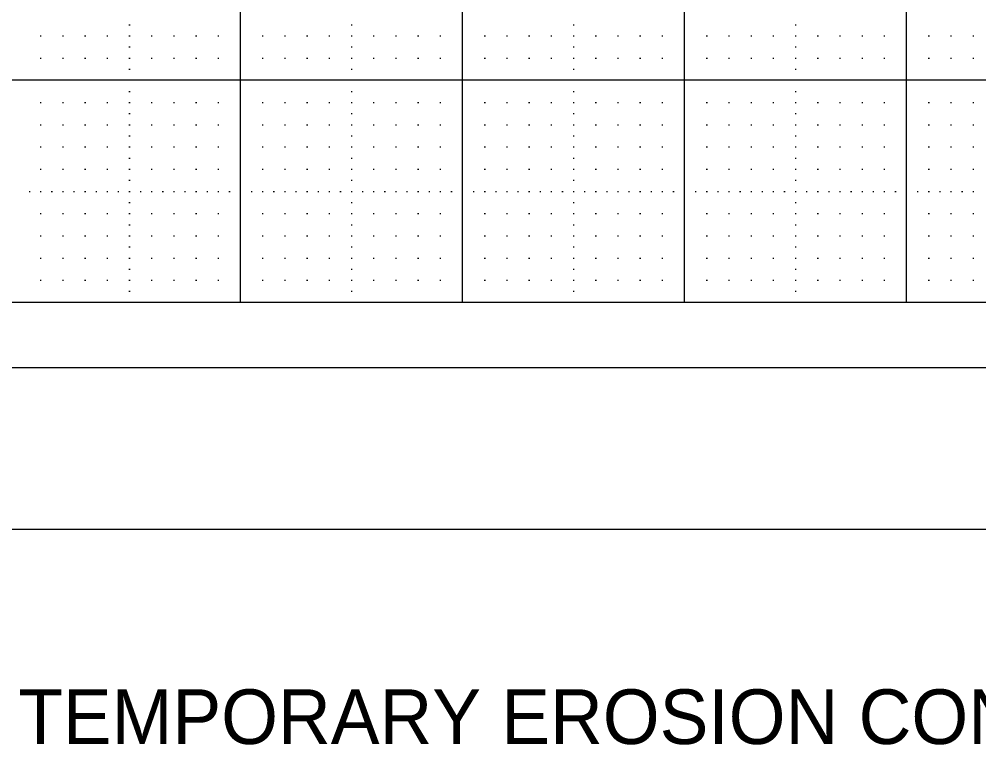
# Model space of a CAD drawing. Extents: x -1.6 to 32.7, y -1.7 to 21.9.
# Drawn here: x 23.748 to 28.07, y -1.698 to 1.568 of the extents above; entities that cross this region are included whole.
import ezdxf

# ---------------------------------------------------------------- set-up
doc = ezdxf.new("R2010")
doc.units = 0
for name, color, linetype in [('Level 1', 7, 'Continuous'), ('Level 4', 7, 'Continuous'), ('Level 5', 7, 'Continuous'), ('Level 63', 7, 'Continuous'), ('R_Border_Dark', 7, 'Continuous'), ('TYPICAL FONT', 7, 'Continuous')]:
    doc.layers.add(name, color=color, linetype=linetype)

msp = doc.modelspace()

# ---------------------------------------------------------------- linework, layer by layer
at = {"layer": 'Level 1'}
msp.add_line((31.617, -0.001), (-0.001, -0.001), dxfattribs=at)
msp.add_lwpolyline([(0.745, 11.3072), (30.745, 11.3072), (30.745, 0.293), (0.745, 0.293)], close=True, dxfattribs=at)
at = {"layer": 'Level 4'}
msp.add_line((31.617, 0.293), (-0.001, 0.293), dxfattribs=at)
at = {"layer": 'Level 5'}
for p, q in [((24.2425, 1.543), (24.2475, 1.543)), ((25.2425, 1.543), (25.2475, 1.543)), ((26.2425, 1.543), (26.2475, 1.543)), ((27.2425, 1.543), (27.2475, 1.543)), ((23.8425, 1.493), (23.8475, 1.493)), ((23.9425, 1.493), (23.9475, 1.493)), ((24.0425, 1.493), (24.0475, 1.493)), ((24.1425, 1.493), (24.1475, 1.493)), ((24.2425, 1.493), (24.2475, 1.493)), ((24.3425, 1.493), (24.3475, 1.493)), ((24.4425, 1.493), (24.4475, 1.493)), ((24.5425, 1.493), (24.5475, 1.493)), ((24.6425, 1.493), (24.6475, 1.493)), ((24.8425, 1.493), (24.8475, 1.493)), ((24.9425, 1.493), (24.9475, 1.493)), ((25.0425, 1.493), (25.0475, 1.493)), ((25.1425, 1.493), (25.1475, 1.493)), ((25.2425, 1.493), (25.2475, 1.493)), ((25.3425, 1.493), (25.3475, 1.493)), ((25.4425, 1.493), (25.4475, 1.493)), ((25.5425, 1.493), (25.5475, 1.493)), ((25.6425, 1.493), (25.6475, 1.493)), ((25.8425, 1.493), (25.8475, 1.493)), ((25.9425, 1.493), (25.9475, 1.493)), ((26.0425, 1.493), (26.0475, 1.493)), ((26.1425, 1.493), (26.1475, 1.493)), ((26.2425, 1.493), (26.2475, 1.493)), ((26.3425, 1.493), (26.3475, 1.493)), ((26.4425, 1.493), (26.4475, 1.493)), ((26.5425, 1.493), (26.5475, 1.493)), ((26.6425, 1.493), (26.6475, 1.493)), ((26.8425, 1.493), (26.8475, 1.493)), ((26.9425, 1.493), (26.9475, 1.493)), ((27.0425, 1.493), (27.0475, 1.493)), ((27.1425, 1.493), (27.1475, 1.493)), ((27.2425, 1.493), (27.2475, 1.493)), ((27.3425, 1.493), (27.3475, 1.493)), ((27.4425, 1.493), (27.4475, 1.493)), ((27.5425, 1.493), (27.5475, 1.493)), ((27.6425, 1.493), (27.6475, 1.493)), ((27.8425, 1.493), (27.8475, 1.493)), ((27.9425, 1.493), (27.9475, 1.493)), ((28.0425, 1.493), (28.0475, 1.493)), ((24.2425, 1.443), (24.2475, 1.443)), ((25.2425, 1.443), (25.2475, 1.443)), ((26.2425, 1.443), (26.2475, 1.443)), ((27.2425, 1.443), (27.2475, 1.443)), ((23.8425, 1.393), (23.8475, 1.393)), ((23.9425, 1.393), (23.9475, 1.393)), ((24.0425, 1.393), (24.0475, 1.393)), ((24.1425, 1.393), (24.1475, 1.393)), ((24.2425, 1.393), (24.2475, 1.393)), ((24.3425, 1.393), (24.3475, 1.393)), ((24.4425, 1.393), (24.4475, 1.393)), ((24.5425, 1.393), (24.5475, 1.393)), ((24.6425, 1.393), (24.6475, 1.393)), ((24.8425, 1.393), (24.8475, 1.393)), ((24.9425, 1.393), (24.9475, 1.393)), ((25.0425, 1.393), (25.0475, 1.393)), ((25.1425, 1.393), (25.1475, 1.393)), ((25.2425, 1.393), (25.2475, 1.393)), ((25.3425, 1.393), (25.3475, 1.393)), ((25.4425, 1.393), (25.4475, 1.393)), ((25.5425, 1.393), (25.5475, 1.393)), ((25.6425, 1.393), (25.6475, 1.393)), ((25.8425, 1.393), (25.8475, 1.393)), ((25.9425, 1.393), (25.9475, 1.393)), ((26.0425, 1.393), (26.0475, 1.393)), ((26.1425, 1.393), (26.1475, 1.393)), ((26.2425, 1.393), (26.2475, 1.393)), ((26.3425, 1.393), (26.3475, 1.393)), ((26.4425, 1.393), (26.4475, 1.393)), ((26.5425, 1.393), (26.5475, 1.393)), ((26.6425, 1.393), (26.6475, 1.393)), ((26.8425, 1.393), (26.8475, 1.393)), ((26.9425, 1.393), (26.9475, 1.393)), ((27.0425, 1.393), (27.0475, 1.393)), ((27.1425, 1.393), (27.1475, 1.393)), ((27.2425, 1.393), (27.2475, 1.393)), ((27.3425, 1.393), (27.3475, 1.393)), ((27.4425, 1.393), (27.4475, 1.393)), ((27.5425, 1.393), (27.5475, 1.393)), ((27.6425, 1.393), (27.6475, 1.393)), ((27.8425, 1.393), (27.8475, 1.393)), ((27.9425, 1.393), (27.9475, 1.393)), ((28.0425, 1.393), (28.0475, 1.393)), ((24.2425, 1.343), (24.2475, 1.343)), ((25.2425, 1.343), (25.2475, 1.343)), ((26.2425, 1.343), (26.2475, 1.343)), ((27.2425, 1.343), (27.2475, 1.343)), ((24.2425, 1.243), (24.2475, 1.243)), ((25.2425, 1.243), (25.2475, 1.243)), ((26.2425, 1.243), (26.2475, 1.243)), ((27.2425, 1.243), (27.2475, 1.243)), ((23.8425, 1.193), (23.8475, 1.193)), ((23.9425, 1.193), (23.9475, 1.193)), ((24.0425, 1.193), (24.0475, 1.193)), ((24.1425, 1.193), (24.1475, 1.193)), ((24.2425, 1.193), (24.2475, 1.193)), ((24.3425, 1.193), (24.3475, 1.193)), ((24.4425, 1.193), (24.4475, 1.193)), ((24.5425, 1.193), (24.5475, 1.193)), ((24.6425, 1.193), (24.6475, 1.193)), ((24.8425, 1.193), (24.8475, 1.193)), ((24.9425, 1.193), (24.9475, 1.193)), ((25.0425, 1.193), (25.0475, 1.193)), ((25.1425, 1.193), (25.1475, 1.193)), ((25.2425, 1.193), (25.2475, 1.193)), ((25.3425, 1.193), (25.3475, 1.193)), ((25.4425, 1.193), (25.4475, 1.193)), ((25.5425, 1.193), (25.5475, 1.193)), ((25.6425, 1.193), (25.6475, 1.193)), ((25.8425, 1.193), (25.8475, 1.193)), ((25.9425, 1.193), (25.9475, 1.193)), ((26.0425, 1.193), (26.0475, 1.193)), ((26.1425, 1.193), (26.1475, 1.193)), ((26.2425, 1.193), (26.2475, 1.193)), ((26.3425, 1.193), (26.3475, 1.193)), ((26.4425, 1.193), (26.4475, 1.193)), ((26.5425, 1.193), (26.5475, 1.193)), ((26.6425, 1.193), (26.6475, 1.193)), ((26.8425, 1.193), (26.8475, 1.193)), ((26.9425, 1.193), (26.9475, 1.193)), ((27.0425, 1.193), (27.0475, 1.193)), ((27.1425, 1.193), (27.1475, 1.193)), ((27.2425, 1.193), (27.2475, 1.193)), ((27.3425, 1.193), (27.3475, 1.193)), ((27.4425, 1.193), (27.4475, 1.193)), ((27.5425, 1.193), (27.5475, 1.193)), ((27.6425, 1.193), (27.6475, 1.193)), ((27.8425, 1.193), (27.8475, 1.193)), ((27.9425, 1.193), (27.9475, 1.193)), ((28.0425, 1.193), (28.0475, 1.193)), ((24.2425, 1.143), (24.2475, 1.143)), ((25.2425, 1.143), (25.2475, 1.143)), ((26.2425, 1.143), (26.2475, 1.143)), ((27.2425, 1.143), (27.2475, 1.143)), ((23.8425, 1.093), (23.8475, 1.093)), ((23.9425, 1.093), (23.9475, 1.093)), ((24.0425, 1.093), (24.0475, 1.093)), ((24.1425, 1.093), (24.1475, 1.093)), ((24.2425, 1.093), (24.2475, 1.093)), ((24.3425, 1.093), (24.3475, 1.093)), ((24.4425, 1.093), (24.4475, 1.093)), ((24.5425, 1.093), (24.5475, 1.093)), ((24.6425, 1.093), (24.6475, 1.093)), ((24.8425, 1.093), (24.8475, 1.093)), ((24.9425, 1.093), (24.9475, 1.093)), ((25.0425, 1.093), (25.0475, 1.093)), ((25.1425, 1.093), (25.1475, 1.093)), ((25.2425, 1.093), (25.2475, 1.093)), ((25.3425, 1.093), (25.3475, 1.093)), ((25.4425, 1.093), (25.4475, 1.093)), ((25.5425, 1.093), (25.5475, 1.093)), ((25.6425, 1.093), (25.6475, 1.093)), ((25.8425, 1.093), (25.8475, 1.093)), ((25.9425, 1.093), (25.9475, 1.093)), ((26.0425, 1.093), (26.0475, 1.093)), ((26.1425, 1.093), (26.1475, 1.093)), ((26.2425, 1.093), (26.2475, 1.093)), ((26.3425, 1.093), (26.3475, 1.093)), ((26.4425, 1.093), (26.4475, 1.093)), ((26.5425, 1.093), (26.5475, 1.093)), ((26.6425, 1.093), (26.6475, 1.093)), ((26.8425, 1.093), (26.8475, 1.093)), ((26.9425, 1.093), (26.9475, 1.093)), ((27.0425, 1.093), (27.0475, 1.093)), ((27.1425, 1.093), (27.1475, 1.093)), ((27.2425, 1.093), (27.2475, 1.093)), ((27.3425, 1.093), (27.3475, 1.093)), ((27.4425, 1.093), (27.4475, 1.093)), ((27.5425, 1.093), (27.5475, 1.093)), ((27.6425, 1.093), (27.6475, 1.093)), ((27.8425, 1.093), (27.8475, 1.093)), ((27.9425, 1.093), (27.9475, 1.093)), ((28.0425, 1.093), (28.0475, 1.093)), ((24.2425, 1.043), (24.2475, 1.043)), ((25.2425, 1.043), (25.2475, 1.043)), ((26.2425, 1.043), (26.2475, 1.043)), ((27.2425, 1.043), (27.2475, 1.043)), ((23.8425, 0.993), (23.8475, 0.993)), ((23.9425, 0.993), (23.9475, 0.993)), ((24.0425, 0.993), (24.0475, 0.993)), ((24.1425, 0.993), (24.1475, 0.993)), ((24.2425, 0.993), (24.2475, 0.993)), ((24.3425, 0.993), (24.3475, 0.993)), ((24.4425, 0.993), (24.4475, 0.993)), ((24.5425, 0.993), (24.5475, 0.993)), ((24.6425, 0.993), (24.6475, 0.993)), ((24.8425, 0.993), (24.8475, 0.993)), ((24.9425, 0.993), (24.9475, 0.993)), ((25.0425, 0.993), (25.0475, 0.993)), ((25.1425, 0.993), (25.1475, 0.993)), ((25.2425, 0.993), (25.2475, 0.993)), ((25.3425, 0.993), (25.3475, 0.993)), ((25.4425, 0.993), (25.4475, 0.993)), ((25.5425, 0.993), (25.5475, 0.993)), ((25.6425, 0.993), (25.6475, 0.993)), ((25.8425, 0.993), (25.8475, 0.993)), ((25.9425, 0.993), (25.9475, 0.993)), ((26.0425, 0.993), (26.0475, 0.993)), ((26.1425, 0.993), (26.1475, 0.993)), ((26.2425, 0.993), (26.2475, 0.993)), ((26.3425, 0.993), (26.3475, 0.993)), ((26.4425, 0.993), (26.4475, 0.993)), ((26.5425, 0.993), (26.5475, 0.993)), ((26.6425, 0.993), (26.6475, 0.993)), ((26.8425, 0.993), (26.8475, 0.993)), ((26.9425, 0.993), (26.9475, 0.993)), ((27.0425, 0.993), (27.0475, 0.993)), ((27.1425, 0.993), (27.1475, 0.993)), ((27.2425, 0.993), (27.2475, 0.993)), ((27.3425, 0.993), (27.3475, 0.993)), ((27.4425, 0.993), (27.4475, 0.993)), ((27.5425, 0.993), (27.5475, 0.993)), ((27.6425, 0.993), (27.6475, 0.993)), ((27.8425, 0.993), (27.8475, 0.993)), ((27.9425, 0.993), (27.9475, 0.993)), ((28.0425, 0.993), (28.0475, 0.993)), ((24.2425, 0.943), (24.2475, 0.943)), ((25.2425, 0.943), (25.2475, 0.943)), ((26.2425, 0.943), (26.2475, 0.943)), ((27.2425, 0.943), (27.2475, 0.943)), ((23.8425, 0.893), (23.8475, 0.893)), ((23.9425, 0.893), (23.9475, 0.893)), ((24.0425, 0.893), (24.0475, 0.893)), ((24.1425, 0.893), (24.1475, 0.893)), ((24.2425, 0.893), (24.2475, 0.893)), ((24.3425, 0.893), (24.3475, 0.893)), ((24.4425, 0.893), (24.4475, 0.893)), ((24.5425, 0.893), (24.5475, 0.893)), ((24.6425, 0.893), (24.6475, 0.893)), ((24.8425, 0.893), (24.8475, 0.893)), ((24.9425, 0.893), (24.9475, 0.893)), ((25.0425, 0.893), (25.0475, 0.893)), ((25.1425, 0.893), (25.1475, 0.893)), ((25.2425, 0.893), (25.2475, 0.893)), ((25.3425, 0.893), (25.3475, 0.893)), ((25.4425, 0.893), (25.4475, 0.893)), ((25.5425, 0.893), (25.5475, 0.893)), ((25.6425, 0.893), (25.6475, 0.893)), ((25.8425, 0.893), (25.8475, 0.893)), ((25.9425, 0.893), (25.9475, 0.893)), ((26.0425, 0.893), (26.0475, 0.893)), ((26.1425, 0.893), (26.1475, 0.893)), ((26.2425, 0.893), (26.2475, 0.893)), ((26.3425, 0.893), (26.3475, 0.893)), ((26.4425, 0.893), (26.4475, 0.893)), ((26.5425, 0.893), (26.5475, 0.893)), ((26.6425, 0.893), (26.6475, 0.893)), ((26.8425, 0.893), (26.8475, 0.893)), ((26.9425, 0.893), (26.9475, 0.893)), ((27.0425, 0.893), (27.0475, 0.893)), ((27.1425, 0.893), (27.1475, 0.893)), ((27.2425, 0.893), (27.2475, 0.893)), ((27.3425, 0.893), (27.3475, 0.893)), ((27.4425, 0.893), (27.4475, 0.893)), ((27.5425, 0.893), (27.5475, 0.893)), ((27.6425, 0.893), (27.6475, 0.893)), ((27.8425, 0.893), (27.8475, 0.893)), ((27.9425, 0.893), (27.9475, 0.893)), ((28.0425, 0.893), (28.0475, 0.893)), ((24.2425, 0.843), (24.2475, 0.843)), ((25.2425, 0.843), (25.2475, 0.843)), ((26.2425, 0.843), (26.2475, 0.843)), ((27.2425, 0.843), (27.2475, 0.843)), ((23.7925, 0.793), (23.7975, 0.793)), ((23.8425, 0.793), (23.8475, 0.793)), ((23.8925, 0.793), (23.8975, 0.793)), ((23.9425, 0.793), (23.9475, 0.793)), ((23.9925, 0.793), (23.9975, 0.793)), ((24.0425, 0.793), (24.0475, 0.793)), ((24.0925, 0.793), (24.0975, 0.793)), ((24.1425, 0.793), (24.1475, 0.793)), ((24.1925, 0.793), (24.1975, 0.793)), ((24.2425, 0.793), (24.2475, 0.793)), ((24.2925, 0.793), (24.2975, 0.793)), ((24.3425, 0.793), (24.3475, 0.793)), ((24.3925, 0.793), (24.3975, 0.793)), ((24.4425, 0.793), (24.4475, 0.793)), ((24.4925, 0.793), (24.4975, 0.793)), ((24.5425, 0.793), (24.5475, 0.793)), ((24.5925, 0.793), (24.5975, 0.793)), ((24.6425, 0.793), (24.6475, 0.793)), ((24.6925, 0.793), (24.6975, 0.793)), ((24.7925, 0.793), (24.7975, 0.793)), ((24.8425, 0.793), (24.8475, 0.793)), ((24.8925, 0.793), (24.8975, 0.793)), ((24.9425, 0.793), (24.9475, 0.793)), ((24.9925, 0.793), (24.9975, 0.793)), ((25.0425, 0.793), (25.0475, 0.793)), ((25.0925, 0.793), (25.0975, 0.793)), ((25.1425, 0.793), (25.1475, 0.793)), ((25.1925, 0.793), (25.1975, 0.793)), ((25.2425, 0.793), (25.2475, 0.793)), ((25.2925, 0.793), (25.2975, 0.793)), ((25.3425, 0.793), (25.3475, 0.793)), ((25.3925, 0.793), (25.3975, 0.793)), ((25.4425, 0.793), (25.4475, 0.793)), ((25.4925, 0.793), (25.4975, 0.793)), ((25.5425, 0.793), (25.5475, 0.793)), ((25.5925, 0.793), (25.5975, 0.793)), ((25.6425, 0.793), (25.6475, 0.793)), ((25.6925, 0.793), (25.6975, 0.793)), ((25.7925, 0.793), (25.7975, 0.793)), ((25.8425, 0.793), (25.8475, 0.793)), ((25.8925, 0.793), (25.8975, 0.793)), ((25.9425, 0.793), (25.9475, 0.793)), ((25.9925, 0.793), (25.9975, 0.793)), ((26.0425, 0.793), (26.0475, 0.793)), ((26.0925, 0.793), (26.0975, 0.793)), ((26.1425, 0.793), (26.1475, 0.793)), ((26.1925, 0.793), (26.1975, 0.793)), ((26.2425, 0.793), (26.2475, 0.793)), ((26.2925, 0.793), (26.2975, 0.793)), ((26.3425, 0.793), (26.3475, 0.793)), ((26.3925, 0.793), (26.3975, 0.793)), ((26.4425, 0.793), (26.4475, 0.793)), ((26.4925, 0.793), (26.4975, 0.793)), ((26.5425, 0.793), (26.5475, 0.793)), ((26.5925, 0.793), (26.5975, 0.793)), ((26.6425, 0.793), (26.6475, 0.793)), ((26.6925, 0.793), (26.6975, 0.793)), ((26.7925, 0.793), (26.7975, 0.793)), ((26.8425, 0.793), (26.8475, 0.793)), ((26.8925, 0.793), (26.8975, 0.793)), ((26.9425, 0.793), (26.9475, 0.793)), ((26.9925, 0.793), (26.9975, 0.793)), ((27.0425, 0.793), (27.0475, 0.793)), ((27.0925, 0.793), (27.0975, 0.793)), ((27.1425, 0.793), (27.1475, 0.793)), ((27.1925, 0.793), (27.1975, 0.793)), ((27.2425, 0.793), (27.2475, 0.793)), ((27.2925, 0.793), (27.2975, 0.793)), ((27.3425, 0.793), (27.3475, 0.793)), ((27.3925, 0.793), (27.3975, 0.793)), ((27.4425, 0.793), (27.4475, 0.793)), ((27.4925, 0.793), (27.4975, 0.793)), ((27.5425, 0.793), (27.5475, 0.793)), ((27.5925, 0.793), (27.5975, 0.793)), ((27.6425, 0.793), (27.6475, 0.793)), ((27.6925, 0.793), (27.6975, 0.793)), ((27.7925, 0.793), (27.7975, 0.793)), ((27.8425, 0.793), (27.8475, 0.793)), ((27.8925, 0.793), (27.8975, 0.793)), ((27.9425, 0.793), (27.9475, 0.793)), ((27.9925, 0.793), (27.9975, 0.793)), ((28.0425, 0.793), (28.0475, 0.793)), ((24.2425, 0.743), (24.2475, 0.743)), ((25.2425, 0.743), (25.2475, 0.743)), ((26.2425, 0.743), (26.2475, 0.743)), ((27.2425, 0.743), (27.2475, 0.743)), ((23.8425, 0.693), (23.8475, 0.693)), ((23.9425, 0.693), (23.9475, 0.693)), ((24.0425, 0.693), (24.0475, 0.693)), ((24.1425, 0.693), (24.1475, 0.693)), ((24.2425, 0.693), (24.2475, 0.693)), ((24.3425, 0.693), (24.3475, 0.693)), ((24.4425, 0.693), (24.4475, 0.693)), ((24.5425, 0.693), (24.5475, 0.693)), ((24.6425, 0.693), (24.6475, 0.693)), ((24.8425, 0.693), (24.8475, 0.693)), ((24.9425, 0.693), (24.9475, 0.693)), ((25.0425, 0.693), (25.0475, 0.693)), ((25.1425, 0.693), (25.1475, 0.693)), ((25.2425, 0.693), (25.2475, 0.693)), ((25.3425, 0.693), (25.3475, 0.693)), ((25.4425, 0.693), (25.4475, 0.693)), ((25.5425, 0.693), (25.5475, 0.693)), ((25.6425, 0.693), (25.6475, 0.693)), ((25.8425, 0.693), (25.8475, 0.693)), ((25.9425, 0.693), (25.9475, 0.693)), ((26.0425, 0.693), (26.0475, 0.693)), ((26.1425, 0.693), (26.1475, 0.693)), ((26.2425, 0.693), (26.2475, 0.693)), ((26.3425, 0.693), (26.3475, 0.693)), ((26.4425, 0.693), (26.4475, 0.693)), ((26.5425, 0.693), (26.5475, 0.693)), ((26.6425, 0.693), (26.6475, 0.693)), ((26.8425, 0.693), (26.8475, 0.693)), ((26.9425, 0.693), (26.9475, 0.693)), ((27.0425, 0.693), (27.0475, 0.693)), ((27.1425, 0.693), (27.1475, 0.693)), ((27.2425, 0.693), (27.2475, 0.693)), ((27.3425, 0.693), (27.3475, 0.693)), ((27.4425, 0.693), (27.4475, 0.693)), ((27.5425, 0.693), (27.5475, 0.693)), ((27.6425, 0.693), (27.6475, 0.693)), ((27.8425, 0.693), (27.8475, 0.693)), ((27.9425, 0.693), (27.9475, 0.693)), ((28.0425, 0.693), (28.0475, 0.693)), ((24.2425, 0.643), (24.2475, 0.643)), ((25.2425, 0.643), (25.2475, 0.643)), ((26.2425, 0.643), (26.2475, 0.643)), ((27.2425, 0.643), (27.2475, 0.643)), ((23.8425, 0.593), (23.8475, 0.593)), ((23.9425, 0.593), (23.9475, 0.593)), ((24.0425, 0.593), (24.0475, 0.593)), ((24.1425, 0.593), (24.1475, 0.593)), ((24.2425, 0.593), (24.2475, 0.593)), ((24.3425, 0.593), (24.3475, 0.593)), ((24.4425, 0.593), (24.4475, 0.593)), ((24.5425, 0.593), (24.5475, 0.593)), ((24.6425, 0.593), (24.6475, 0.593)), ((24.8425, 0.593), (24.8475, 0.593)), ((24.9425, 0.593), (24.9475, 0.593)), ((25.0425, 0.593), (25.0475, 0.593)), ((25.1425, 0.593), (25.1475, 0.593)), ((25.2425, 0.593), (25.2475, 0.593)), ((25.3425, 0.593), (25.3475, 0.593)), ((25.4425, 0.593), (25.4475, 0.593)), ((25.5425, 0.593), (25.5475, 0.593)), ((25.6425, 0.593), (25.6475, 0.593)), ((25.8425, 0.593), (25.8475, 0.593)), ((25.9425, 0.593), (25.9475, 0.593)), ((26.0425, 0.593), (26.0475, 0.593)), ((26.1425, 0.593), (26.1475, 0.593)), ((26.2425, 0.593), (26.2475, 0.593)), ((26.3425, 0.593), (26.3475, 0.593)), ((26.4425, 0.593), (26.4475, 0.593)), ((26.5425, 0.593), (26.5475, 0.593)), ((26.6425, 0.593), (26.6475, 0.593)), ((26.8425, 0.593), (26.8475, 0.593)), ((26.9425, 0.593), (26.9475, 0.593)), ((27.0425, 0.593), (27.0475, 0.593)), ((27.1425, 0.593), (27.1475, 0.593)), ((27.2425, 0.593), (27.2475, 0.593)), ((27.3425, 0.593), (27.3475, 0.593)), ((27.4425, 0.593), (27.4475, 0.593)), ((27.5425, 0.593), (27.5475, 0.593)), ((27.6425, 0.593), (27.6475, 0.593)), ((27.8425, 0.593), (27.8475, 0.593)), ((27.9425, 0.593), (27.9475, 0.593)), ((28.0425, 0.593), (28.0475, 0.593)), ((24.2425, 0.543), (24.2475, 0.543)), ((25.2425, 0.543), (25.2475, 0.543)), ((26.2425, 0.543), (26.2475, 0.543)), ((27.2425, 0.543), (27.2475, 0.543)), ((23.8425, 0.493), (23.8475, 0.493)), ((23.9425, 0.493), (23.9475, 0.493)), ((24.0425, 0.493), (24.0475, 0.493)), ((24.1425, 0.493), (24.1475, 0.493)), ((24.2425, 0.493), (24.2475, 0.493)), ((24.3425, 0.493), (24.3475, 0.493)), ((24.4425, 0.493), (24.4475, 0.493)), ((24.5425, 0.493), (24.5475, 0.493)), ((24.6425, 0.493), (24.6475, 0.493)), ((24.8425, 0.493), (24.8475, 0.493)), ((24.9425, 0.493), (24.9475, 0.493)), ((25.0425, 0.493), (25.0475, 0.493)), ((25.1425, 0.493), (25.1475, 0.493)), ((25.2425, 0.493), (25.2475, 0.493)), ((25.3425, 0.493), (25.3475, 0.493)), ((25.4425, 0.493), (25.4475, 0.493)), ((25.5425, 0.493), (25.5475, 0.493)), ((25.6425, 0.493), (25.6475, 0.493)), ((25.8425, 0.493), (25.8475, 0.493)), ((25.9425, 0.493), (25.9475, 0.493)), ((26.0425, 0.493), (26.0475, 0.493)), ((26.1425, 0.493), (26.1475, 0.493)), ((26.2425, 0.493), (26.2475, 0.493)), ((26.3425, 0.493), (26.3475, 0.493)), ((26.4425, 0.493), (26.4475, 0.493)), ((26.5425, 0.493), (26.5475, 0.493)), ((26.6425, 0.493), (26.6475, 0.493)), ((26.8425, 0.493), (26.8475, 0.493)), ((26.9425, 0.493), (26.9475, 0.493)), ((27.0425, 0.493), (27.0475, 0.493)), ((27.1425, 0.493), (27.1475, 0.493)), ((27.2425, 0.493), (27.2475, 0.493)), ((27.3425, 0.493), (27.3475, 0.493)), ((27.4425, 0.493), (27.4475, 0.493)), ((27.5425, 0.493), (27.5475, 0.493)), ((27.6425, 0.493), (27.6475, 0.493)), ((27.8425, 0.493), (27.8475, 0.493)), ((27.9425, 0.493), (27.9475, 0.493)), ((28.0425, 0.493), (28.0475, 0.493)), ((24.2425, 0.443), (24.2475, 0.443)), ((25.2425, 0.443), (25.2475, 0.443)), ((26.2425, 0.443), (26.2475, 0.443)), ((27.2425, 0.443), (27.2475, 0.443)), ((23.8425, 0.393), (23.8475, 0.393)), ((23.9425, 0.393), (23.9475, 0.393)), ((24.0425, 0.393), (24.0475, 0.393)), ((24.1425, 0.393), (24.1475, 0.393)), ((24.2425, 0.393), (24.2475, 0.393)), ((24.3425, 0.393), (24.3475, 0.393)), ((24.4425, 0.393), (24.4475, 0.393)), ((24.5425, 0.393), (24.5475, 0.393)), ((24.6425, 0.393), (24.6475, 0.393)), ((24.8425, 0.393), (24.8475, 0.393)), ((24.9425, 0.393), (24.9475, 0.393)), ((25.0425, 0.393), (25.0475, 0.393)), ((25.1425, 0.393), (25.1475, 0.393)), ((25.2425, 0.393), (25.2475, 0.393)), ((25.3425, 0.393), (25.3475, 0.393)), ((25.4425, 0.393), (25.4475, 0.393)), ((25.5425, 0.393), (25.5475, 0.393)), ((25.6425, 0.393), (25.6475, 0.393)), ((25.8425, 0.393), (25.8475, 0.393)), ((25.9425, 0.393), (25.9475, 0.393)), ((26.0425, 0.393), (26.0475, 0.393)), ((26.1425, 0.393), (26.1475, 0.393)), ((26.2425, 0.393), (26.2475, 0.393)), ((26.3425, 0.393), (26.3475, 0.393)), ((26.4425, 0.393), (26.4475, 0.393)), ((26.5425, 0.393), (26.5475, 0.393)), ((26.6425, 0.393), (26.6475, 0.393)), ((26.8425, 0.393), (26.8475, 0.393)), ((26.9425, 0.393), (26.9475, 0.393)), ((27.0425, 0.393), (27.0475, 0.393)), ((27.1425, 0.393), (27.1475, 0.393)), ((27.2425, 0.393), (27.2475, 0.393)), ((27.3425, 0.393), (27.3475, 0.393)), ((27.4425, 0.393), (27.4475, 0.393)), ((27.5425, 0.393), (27.5475, 0.393)), ((27.6425, 0.393), (27.6475, 0.393)), ((27.8425, 0.393), (27.8475, 0.393)), ((27.9425, 0.393), (27.9475, 0.393)), ((28.0425, 0.393), (28.0475, 0.393)), ((24.2425, 0.343), (24.2475, 0.343)), ((25.2425, 0.343), (25.2475, 0.343)), ((26.2425, 0.343), (26.2475, 0.343)), ((27.2425, 0.343), (27.2475, 0.343))]:
    msp.add_line(p, q, dxfattribs=at)
at = {"layer": 'Level 63'}
msp.add_lwpolyline([(-1.598, -0.727), (32.402, -0.727), (32.402, 21.273), (-1.598, 21.273)], close=True, dxfattribs=at)
msp.add_lwpolyline([(30.745, 8.293), (30.745, 0.293), (0.745, 0.293), (0.745, 8.293)], dxfattribs=at)
at = {"layer": 'R_Border_Dark'}
for p, q in [((24.745, 0.293), (24.745, 11.3072)), ((25.745, 0.293), (25.745, 11.3072)), ((26.745, 0.293), (26.745, 11.3072)), ((27.745, 0.293), (27.745, 11.3072)), ((31.617, 1.293), (-0.001, 1.293))]:
    msp.add_line(p, q, dxfattribs=at)
msp.add_lwpolyline([(30.745, 8.293), (30.745, 0.293), (0.745, 0.293), (0.745, 8.293)], dxfattribs=at)

# ---------------------------------------------------------------- texts
at = {"layer": 'TYPICAL FONT'}
msp.add_text('TEMPORARY EROSION CONTROL DETAILS', height=0.246094, dxfattribs=at).set_placement((23.7436, -1.6948))

doc.saveas('drawing.dxf')
